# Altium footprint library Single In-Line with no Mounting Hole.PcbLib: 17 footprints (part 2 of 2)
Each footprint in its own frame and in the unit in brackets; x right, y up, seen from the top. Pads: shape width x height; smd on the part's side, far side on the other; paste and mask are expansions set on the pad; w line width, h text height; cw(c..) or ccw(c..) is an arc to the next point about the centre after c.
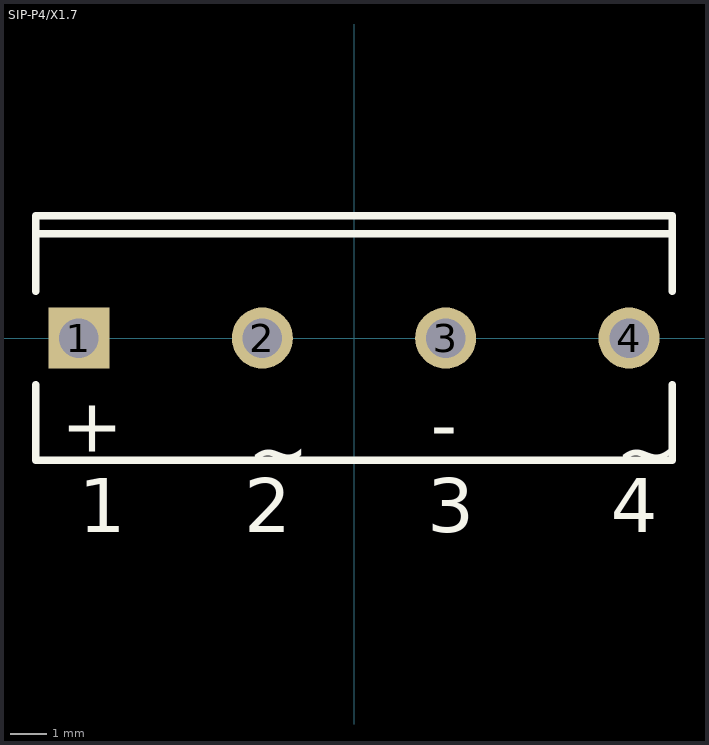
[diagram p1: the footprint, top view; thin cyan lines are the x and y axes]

## SIP-P4/X1.7 [mm]
pads (4):
  rect 1.7x1.7 hole 1.1: 1(-7.65,0)
  round 1.7 hole 1.1: 2(-2.55,0) 3(2.55,0) 4(7.65,0)
Top Overlay:
  lines w0.2: -8.85,-1.3 -8.85,-3.4 8.85,-3.4 8.85,-1.3 ; -8.85,1.3 -8.85,3.4 8.85,3.4 8.85,1.3 ; -8.85,2.9 8.85,2.9
  text "1" at -7.65,-5.4 h1.5
  text "2" at -3.058,-5.4 h1.5
  text "3" at 2.042,-5.4 h1.5
  text "4" at 7.142,-5.4 h1.5
  text "-" at 2.13,-3.15 h1.5
  text "+" at -8.14,-3.16 h1.5
  text "~" at -2.97,-3.9 h1.5
  text "~" at 7.27,-3.9 h1.5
